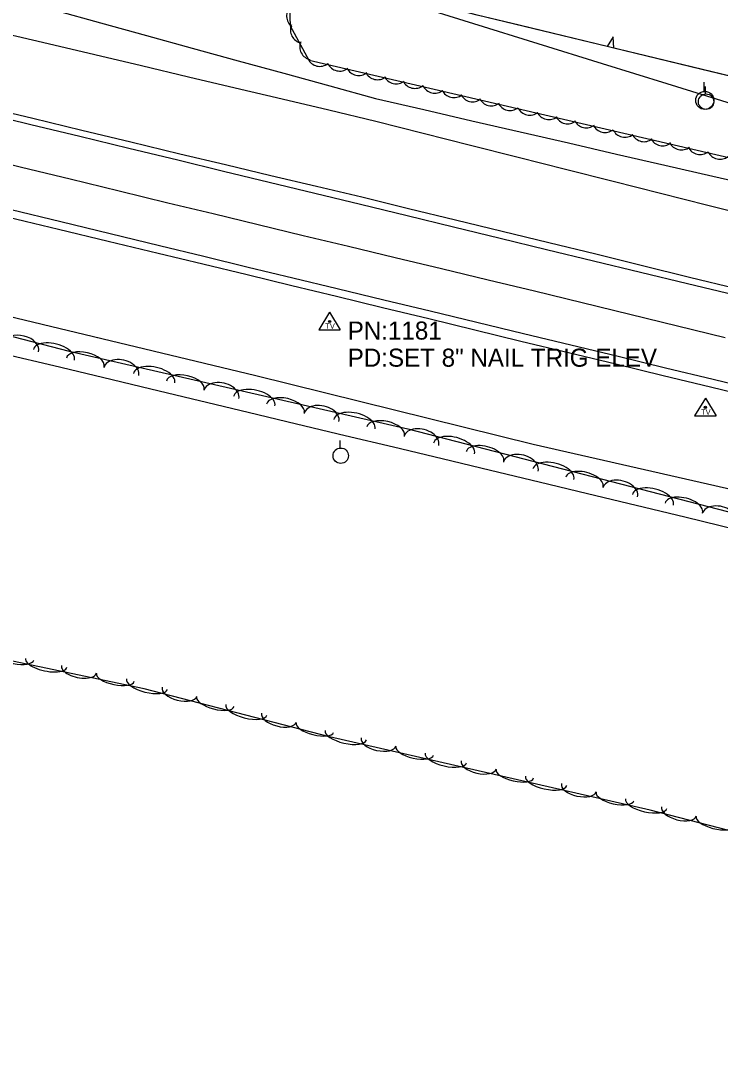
# Model space of a CAD drawing. Extents: x 1441650 to 1491889, y 345904 to 358319.
# Drawn here: x 1458942.8 to 1459136.3, y 351176 to 351464.9 of the extents above; entities that cross this region are included whole.
import ezdxf

# ---------------------------------------------------------------- set-up
doc = ezdxf.new("R2010")
doc.units = 0
for name, color, linetype in [('S_DITCHLINE', 7, 'Continuous'), ('S_EDGE_PAVEMENT', 7, 'Continuous'), ('S_PAVEMENT_CROWN', 7, 'Continuous'), ('S_SECONDARY_CTL', 7, 'Continuous'), ('S_SECONDARY_CTL_ANNOT', 7, 'Continuous'), ('S_SHOULDER', 7, 'Continuous'), ('S_STREAM', 7, 'Continuous'), ('S_TREE', 7, 'Continuous'), ('S_UTILITY_POLE', 7, 'Continuous')]:
    doc.layers.add(name, color=color, linetype=linetype)

msp = doc.modelspace()

# ---------------------------------------------------------------- linework, layer by layer
at = {"layer": 'S_DITCHLINE'}
for points in [[(1458952.14, 351467.83), (1458964.82, 351464.34), (1458977.5, 351460.85), (1458990.18, 351457.35), (1459002.86, 351453.86), (1459015.54, 351450.37), (1459028.22, 351446.87), (1459040.9, 351443.38), (1459054.24, 351440.31), (1459067.58, 351437.24), (1459080.92, 351434.17), (1459094.26, 351431.1), (1459107.6, 351428.03), (1459120.94, 351424.96), (1459134.28, 351421.9), (1459147.62, 351418.83)], [(1458937.31, 351461.69), (1458950.27, 351458.62), (1458963.22, 351455.55), (1458976.18, 351452.49), (1458989.13, 351449.42), (1459002.08, 351446.35), (1459015.04, 351443.29), (1459027.99, 351440.22), (1459040.95, 351437.15), (1459054.08, 351433.83), (1459067.22, 351430.51), (1459080.36, 351427.19), (1459093.49, 351423.87), (1459106.63, 351420.55), (1459119.76, 351417.23), (1459132.9, 351413.91), (1459146.03, 351410.59)]]:
    msp.add_lwpolyline(points, dxfattribs=at)
at = {"layer": 'S_EDGE_PAVEMENT'}
for points in [[(1458931.95, 351439.51), (1458945.51, 351436.23), (1458959.06, 351432.95), (1458972.61, 351429.67), (1458986.16, 351426.39), (1458998.81, 351423.33), (1459011.45, 351420.26), (1459024.09, 351417.19), (1459036.73, 351414.12), (1459049.61, 351410.99), (1459062.49, 351407.87), (1459075.37, 351404.74), (1459088.24, 351401.62), (1459101.26, 351398.48), (1459114.27, 351395.34), (1459127.28, 351392.2), (1459140.3, 351389.07)], [(1458940.11, 351412.73), (1458953.77, 351409.4), (1458967.43, 351406.07), (1458981.1, 351402.74), (1458993.39, 351399.76), (1459005.69, 351396.78), (1459017.99, 351393.8), (1459030.29, 351390.82), (1459043.17, 351387.72), (1459056.05, 351384.62), (1459068.93, 351381.52), (1459081.81, 351378.42), (1459094.94, 351375.25), (1459108.06, 351372.08), (1459121.18, 351368.91), (1459134.3, 351365.73), (1459147.59, 351362.5)]]:
    msp.add_lwpolyline(points, dxfattribs=at)
at = {"layer": 'S_PAVEMENT_CROWN'}
msp.add_lwpolyline([(1458929.4, 351427.7), (1458942.9, 351424.42), (1458956.41, 351421.14), (1458969.92, 351417.86), (1458983.43, 351414.58), (1458995.93, 351411.57), (1459008.43, 351408.56), (1459020.92, 351405.54), (1459033.42, 351402.53), (1459046.29, 351399.44), (1459059.16, 351396.36), (1459072.03, 351393.27), (1459084.89, 351390.19), (1459098.08, 351386.95), (1459111.27, 351383.72), (1459124.46, 351380.49), (1459137.65, 351377.26)], dxfattribs=at)
at = {"layer": 'S_SECONDARY_CTL'}
for p, q in [((1459028.2, 351384.31), (1459025.19, 351379.36)), ((1459028.2, 351384.31), (1459031.15, 351379.36)), ((1459025.19, 351379.36), (1459031.15, 351379.36)), ((1459132.2, 351360.54), (1459129.19, 351355.58)), ((1459132.2, 351360.54), (1459135.14, 351355.58)), ((1459129.19, 351355.58), (1459135.14, 351355.58))]:
    msp.add_line(p, q, dxfattribs=at)
for centre, radius in [((1459028.2, 351381.7), 0.311), ((1459028.2, 351381.7), 0.183), ((1459028.2, 351381.7), 0.103), ((1459132.2, 351357.93), 0.311), ((1459132.2, 351357.93), 0.183), ((1459132.2, 351357.93), 0.103)]:
    msp.add_circle(centre, radius, dxfattribs=at)
at = {"layer": 'S_SHOULDER'}
for points in [[(1458932.45, 351441.22), (1458946.03, 351437.95), (1458959.62, 351434.68), (1458973.2, 351431.41), (1458986.78, 351428.13), (1458999.37, 351425.14), (1459011.97, 351422.14), (1459024.56, 351419.14), (1459037.15, 351416.15), (1459050.07, 351413), (1459063, 351409.86), (1459075.92, 351406.72), (1459088.84, 351403.57), (1459101.83, 351400.39), (1459114.81, 351397.2), (1459127.8, 351394.01), (1459140.79, 351390.83)], [(1458939.31, 351410.59), (1458953.13, 351407.28), (1458966.95, 351403.97), (1458980.77, 351400.65), (1458993.1, 351397.67), (1459005.42, 351394.69), (1459017.74, 351391.71), (1459030.06, 351388.74), (1459042.83, 351385.62), (1459055.61, 351382.5), (1459068.38, 351379.39), (1459081.15, 351376.27), (1459094.27, 351373.12), (1459107.39, 351369.96), (1459120.51, 351366.81), (1459133.63, 351363.66), (1459146.91, 351360.45)]]:
    msp.add_lwpolyline(points, dxfattribs=at)
at = {"layer": 'S_STREAM'}
msp.add_lwpolyline([(1458578.61, 351464.35), (1458632.28, 351453), (1458720.19, 351434.47), (1458817.6, 351411.03), (1458920.11, 351387.75), (1459007.82, 351366.75), (1459084.49, 351347.81), (1459170.91, 351328.16), (1459288.39, 351301.52), (1459381.79, 351277.55), (1459486.81, 351250.35), (1459558.24, 351231.73), (1459664.82, 351202.09)], dxfattribs=at)
at = {"layer": 'S_TREE'}
for p, q in [((1459106.68, 351460.46), (1459104.98, 351457.79)), ((1459106.89, 351457.33), (1459106.68, 351460.46))]:
    msp.add_line(p, q, dxfattribs=at)
for points in [[(1459069.51, 351574.99), (1459127.34, 351579.7), (1459169.83, 351513.3), (1459202.3, 351490.62), (1459346.8, 351460.5), (1459366.42, 351447.46), (1459366.82, 351430.61), (1459359.57, 351408.24), (1459344.81, 351401.56), (1459258.75, 351420.69), (1459069.07, 351466.45), (1459055.48, 351469.97), (1459050.78, 351481.36), (1459069.16, 351573.69)], [(1459015.27, 351509.45), (1459014.9, 351495.12), (1459014.53, 351480.79), (1459032.35, 351475.25), (1459050.18, 351469.71), (1459068, 351464.18), (1459085.83, 351458.64), (1459103.65, 351453.1), (1459121.48, 351447.56), (1459139.31, 351442.03), (1459157.13, 351436.49), (1459176.42, 351432.29), (1459195.7, 351428.09), (1459214.98, 351423.89), (1459234.27, 351419.69), (1459253.55, 351415.49), (1459272.84, 351411.29), (1459292.12, 351407.09), (1459311.41, 351402.89), (1459330.69, 351398.69), (1459349.98, 351394.49), (1459369.26, 351390.29), (1459388.55, 351386.09)], [(1459015.27, 351509.45), (1459014.9, 351495.12), (1459014.53, 351480.79), (1459032.35, 351475.25), (1459050.18, 351469.71), (1459068, 351464.18), (1459085.83, 351458.64), (1459103.65, 351453.1), (1459121.48, 351447.56), (1459139.31, 351442.03), (1459157.13, 351436.49), (1459176.42, 351432.29), (1459195.7, 351428.09), (1459214.98, 351423.89), (1459234.27, 351419.69), (1459253.55, 351415.49), (1459272.84, 351411.29), (1459292.12, 351407.09), (1459311.41, 351402.89), (1459330.69, 351398.69), (1459349.98, 351394.49), (1459369.26, 351390.29), (1459388.55, 351386.09)], [(1459356.44, 351408.6), (1459351.73, 351390.83), (1459338.68, 351386.01), (1459319.31, 351385.01), (1459187.54, 351415.64), (1459022.49, 351453.9), (1459017.4, 351463.42), (1459016.94, 351476.87)], [(1459080.68, 351463.65), (1459069.07, 351466.45), (1459056.43, 351469.73)], [(1459104.98, 351457.79), (1459080.68, 351463.65)], [(1459131.2, 351451.46), (1459106.89, 351457.33)], [(1459155.5, 351445.6), (1459131.2, 351451.46)], [(1458663.18, 351448.03), (1458711.01, 351435.73), (1458759.57, 351425.5), (1458796.96, 351415.82), (1458856.35, 351399.3), (1458956.09, 351373.48), (1459049.81, 351352.01), (1459148.97, 351326.34), (1459247.8, 351301.46), (1459338.76, 351279.57), (1459440.78, 351257.04), (1459527.02, 351234.71), (1459625.47, 351213.15), (1459671.91, 351201.13), (1459683.42, 351198.15)], [(1458938.47, 351372.7), (1458951.9, 351369.49), (1458965.32, 351366.27), (1458978.75, 351363.06), (1458992.18, 351359.85), (1459005.61, 351356.63), (1459019.03, 351353.42), (1459032.46, 351350.21), (1459045.89, 351346.99), (1459059.32, 351343.78), (1459072.75, 351340.57), (1459086.17, 351337.35), (1459099.6, 351334.14), (1459113.03, 351330.93), (1459126.46, 351327.71), (1459146.01, 351322.83)], [(1458938.47, 351372.7), (1458951.9, 351369.49), (1458965.32, 351366.27), (1458978.75, 351363.06), (1458992.18, 351359.85), (1459005.61, 351356.63), (1459019.03, 351353.42), (1459032.46, 351350.21), (1459045.89, 351346.99), (1459059.32, 351343.78), (1459072.75, 351340.57), (1459086.17, 351337.35), (1459099.6, 351334.14), (1459113.03, 351330.93), (1459126.46, 351327.71), (1459146.01, 351322.83)], [(1459653.76, 351114.56), (1459499.42, 351153.65), (1459384.1, 351181.62), (1459274.65, 351206.88), (1459222.5, 351219.2), (1459116.91, 351246.53), (1459028.16, 351266.78), (1458976.84, 351280.06), (1458875.39, 351301.41), (1458841.5, 351311.25), (1458791.59, 351327.01), (1458699.46, 351346.83)]]:
    msp.add_lwpolyline(points, dxfattribs=at)
for centre, major_axis, ratio, start_param, end_param in [((1459019.93, 351466.17), (0.12, -3.64), 0.999997, 3.825789, 5.598989), ((1459020.99, 351462.35), (1.72, -3.21), 0.999994, 3.825788, 5.598989), ((1459023.55, 351457.72), (1.72, -3.21), 0.999994, 3.825788, 5.598989), ((1459025.49, 351455.94), (2.06, -3.01), 0.999989, 4.568344, 6.341545), ((1459030.99, 351454.63), (2.06, -3.01), 0.999989, 4.568344, 6.341545), ((1459036.29, 351453.4), (2.06, -3.01), 0.999989, 4.568344, 6.341545), ((1459041.46, 351452.24), (2.06, -3.01), 0.999989, 4.568344, 6.341545), ((1459046.62, 351451.12), (2.06, -3.01), 0.999989, 4.568344, 6.341545), ((1459051.8, 351449.84), (2.06, -3.01), 0.999989, 4.568344, 6.341545), ((1459057.3, 351448.53), (2.06, -3.01), 0.999989, 4.568344, 6.341545), ((1459062.6, 351447.3), (2.06, -3.01), 0.999989, 4.568344, 6.341545), ((1459067.77, 351446.14), (2.06, -3.01), 0.999989, 4.568344, 6.341545), ((1459072.94, 351445.02), (2.06, -3.01), 0.999989, 4.568344, 6.341545), ((1459078.12, 351443.74), (2.06, -3.01), 0.999989, 4.568344, 6.341545), ((1459083.61, 351442.43), (2.06, -3.01), 0.999989, 4.568344, 6.341545), ((1459088.91, 351441.2), (2.06, -3.01), 0.999989, 4.568344, 6.341545), ((1459094.08, 351440.04), (2.06, -3.01), 0.999989, 4.568344, 6.341545), ((1459099.25, 351438.92), (2.06, -3.01), 0.999989, 4.568344, 6.341545), ((1459104.43, 351437.64), (2.06, -3.01), 0.999989, 4.568344, 6.341545), ((1459109.92, 351436.33), (2.06, -3.01), 0.999989, 4.568344, 6.341545), ((1459115.22, 351435.1), (2.06, -3.01), 0.999989, 4.568344, 6.341545), ((1459120.39, 351433.94), (2.06, -3.01), 0.999989, 4.568344, 6.341545), ((1459125.56, 351432.82), (2.06, -3.01), 0.999989, 4.568344, 6.341545), ((1459130.74, 351431.54), (2.06, -3.01), 0.999989, 4.568344, 6.341545), ((1459136.23, 351430.24), (2.06, -3.01), 0.999989, 4.568344, 6.341545), ((1458942.86, 351374.55), (-4.8, 1.24), 0.654285, 3.141673, 6.283265), ((1458951.88, 351372.48), (-5.68, 1.47), 0.525176, 3.141643, 6.283236), ((1458960.55, 351370.38), (-5.21, 1.19), 0.516227, 3.140924, 6.282516), ((1458970.54, 351367.83), (-4.83, 1.1), 0.654294, 3.140505, 6.282098), ((1458979.62, 351366.01), (-5.72, 1.31), 0.525183, 3.140903, 6.282496), ((1458988.26, 351364.03), (-5.21, 1.19), 0.516227, 3.140924, 6.282516), ((1458998.25, 351361.49), (-4.83, 1.1), 0.654294, 3.140505, 6.282098), ((1459007.33, 351359.66), (-5.72, 1.31), 0.525183, 3.140903, 6.282496), ((1459015.97, 351357.68), (-5.21, 1.19), 0.516227, 3.140924, 6.282516), ((1459025.96, 351355.14), (-4.83, 1.1), 0.654294, 3.140505, 6.282098), ((1459035.04, 351353.31), (-5.72, 1.31), 0.525183, 3.140903, 6.282496), ((1459043.68, 351351.33), (-5.21, 1.19), 0.516227, 3.140924, 6.282516), ((1459053.58, 351348.68), (-4.8, 1.24), 0.654285, 3.141163, 6.282756), ((1459062.61, 351346.6), (-5.68, 1.47), 0.525177, 3.14132, 6.282913), ((1459071.19, 351344.38), (-5.18, 1.34), 0.516221, 3.141328, 6.282921), ((1459081.1, 351341.56), (-4.8, 1.24), 0.654285, 3.141163, 6.282756), ((1459090.13, 351339.48), (-5.68, 1.47), 0.525177, 3.14132, 6.282913), ((1459098.71, 351337.26), (-5.18, 1.34), 0.516221, 3.141328, 6.282921), ((1459108.62, 351334.44), (-4.8, 1.24), 0.654285, 3.141163, 6.282756), ((1459117.65, 351332.36), (-5.68, 1.47), 0.525177, 3.14132, 6.282913), ((1459126.23, 351330.13), (-5.18, 1.34), 0.516221, 3.141328, 6.282921), ((1459136.14, 351327.31), (-4.8, 1.24), 0.654285, 3.141163, 6.282756), ((1458941.07, 351289.12), (5.23, -1.1), 0.381121, 3.142495, 6.284087), ((1458949.75, 351287.29), (5.74, -1.21), 0.387733, 3.142516, 6.284109), ((1458958.85, 351285.56), (4.85, -1.02), 0.483052, 3.142867, 6.28446), ((1458968.89, 351283.26), (5.23, -1.1), 0.381121, 3.142495, 6.284087), ((1458977.63, 351281.4), (5.68, -1.47), 0.38764, 3.141593, 6.283185), ((1458986.64, 351279.26), (4.8, -1.24), 0.482937, 3.141593, 6.283185), ((1458996.57, 351276.5), (5.18, -1.34), 0.38103, 3.141593, 6.283185), ((1459005.15, 351274.28), (5.68, -1.47), 0.38764, 3.141593, 6.283185), ((1459014.16, 351272.13), (4.8, -1.24), 0.482937, 3.141593, 6.283185), ((1459024.09, 351269.38), (5.18, -1.34), 0.38103, 3.141593, 6.283185), ((1459032.66, 351267.28), (5.72, -1.31), 0.387643, 3.141593, 6.283185), ((1459041.73, 351265.4), (4.83, -1.1), 0.482941, 3.141593, 6.283185), ((1459051.73, 351262.93), (5.21, -1.19), 0.381032, 3.141593, 6.283185), ((1459060.38, 351260.96), (5.72, -1.31), 0.387643, 3.141593, 6.283185), ((1459069.44, 351259.08), (4.83, -1.1), 0.482941, 3.141593, 6.283185), ((1459079.45, 351256.61), (5.21, -1.19), 0.381032, 3.141593, 6.283185), ((1459088.09, 351254.64), (5.72, -1.31), 0.387643, 3.141593, 6.283185), ((1459097.16, 351252.76), (4.83, -1.1), 0.482941, 3.141593, 6.283185), ((1459107.16, 351250.29), (5.21, -1.19), 0.381032, 3.141593, 6.283185), ((1459115.81, 351248.31), (5.72, -1.31), 0.387643, 3.141593, 6.283185), ((1459124.87, 351246.2), (4.8, -1.24), 0.482937, 3.141593, 6.283185), ((1459134.8, 351243.44), (5.18, -1.34), 0.38103, 3.141593, 6.283185)]:
    msp.add_ellipse(centre, major_axis=major_axis, ratio=ratio, start_param=start_param, end_param=end_param, dxfattribs=at)
at = {"layer": 'S_UTILITY_POLE'}
for p, q in [((1459131.89, 351445.4), (1459131.89, 351447.88)), ((1459132.25, 351444.66), (1459132.25, 351446.76)), ((1459031.15, 351346.73), (1459031.15, 351348.83))]:
    msp.add_line(p, q, dxfattribs=at)
for centre, radius in [((1459132.03, 351442.88), 2.5), ((1459132.38, 351442.52), 2.13), ((1459031.27, 351344.58), 2.13)]:
    msp.add_circle(centre, radius, dxfattribs=at)

# ---------------------------------------------------------------- texts
at = {"layer": 'S_SECONDARY_CTL'}
for p in [(1459027, 351379.69), (1459130.99, 351355.92)]:
    msp.add_text('TV', height=1.5, rotation=360, dxfattribs=at).set_placement(p)
at = {"layer": 'S_SECONDARY_CTL_ANNOT'}
for s, p in [('PN:1181', (1459033.2, 351376.7)), ('PD:SET 8" NAIL TRIG ELEV', (1459033.2, 351369.2))]:
    msp.add_text(s, height=5, dxfattribs=at).set_placement(p)

doc.saveas('drawing.dxf')
